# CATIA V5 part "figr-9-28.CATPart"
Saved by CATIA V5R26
Part number: Part1
Bounding box of the stored display mesh (mm): x -75 to 75, y -50 to 50, z 0 to 40
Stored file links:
  D:\_Deepak\CATIA\CATIA V5-6R2016_Deepak\Resources\Part files\Partfiles\c09_catia_v5_6r2016_prt\figr-9-28.CATPart
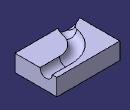
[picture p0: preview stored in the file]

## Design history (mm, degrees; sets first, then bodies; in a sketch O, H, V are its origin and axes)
Body1 (main body)
  Sketch1 on xy-plane, origin (0, 0, 0), H (1, 0, 0), V (0, 1, 0)
    line L1 (-75, 50) -> (75, 50)
    line L2 (75, 50) -> (75, -50)
    line L3 (75, -50) -> (-75, -50)
    line L4 (-75, -50) -> (-75, 50)
    axis line L5 (75, -50) -> (-75, 50)
    length L2 = 100
    length L3 = 150
    horizontal: L1 H, L3 H
    vertical: L2 V, L4 V
    midpoint: O L5
  Pad1: profile Sketch1, direction (0, 0, 1), length 40
  Sketch2 on face of Pad1, origin (75, 0, 0), H (0, 1, 0), V (0, 0, 1)
    arc A1 centre (24.1478, 40) radius 14.6047 from (9.543, 40) to (38.7525, 40) ccw
    point P1 (24.1478, 40)
    reference projected point E1 (24.1478, 40) from vertex of Sketch3
    line L1 (9.543, 40) -> (38.7525, 40)
    coincidence: P1 E1
    horizontal: L1 H
  Sketch3 on face of Pad1, origin (0, 0, 40), H (1, 0, 0), V (0, 1, 0)
    point P1 (75, 24.1478)
    line L1 (75, 24.1478) -> (28.6577, 24.1478)
    arc A1 centre (28.6577, -39.2062) radius 63.354 from (28.6577, 24.1478) to (-33.8383, -28.8149) ccw
    arc A2 centre (-62.192, -24.1005) radius 28.7429 from (-33.8383, -28.8149) to (-49.7271, -50) cw
    point P6 (-49.7271, -50)
    reference projected line E1 (75, -50) -> (75, 50) from edge [face of Pad1 | face of Pad1]
    reference projected line E2 (-75, -50) -> (75, -50) from edge [face of Pad1 | face of Pad1]
    horizontal: L1 H
    tangency: A1 L1, A2 A1
    coincidence: P1 E1, P6 E2
  Slot1: profile Sketch2, centre curve Sketch3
